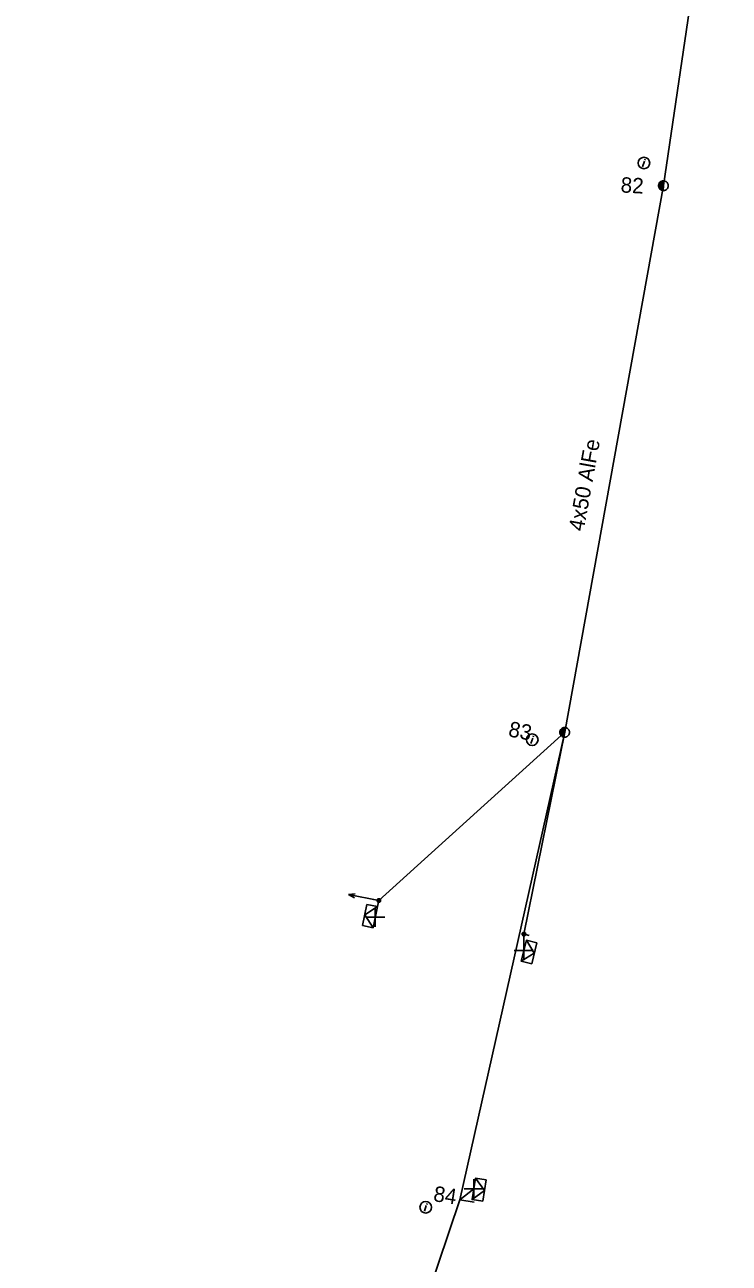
# Model space of a CAD drawing. Extents: x -544780 to -541582, y -1198995 to -1196551.
# Drawn here: x -542579.2 to -542533.5, y -1198149.8 to -1198069.4 of the extents above; entities that cross this region are included whole.
import ezdxf

# ---------------------------------------------------------------- set-up
doc = ezdxf.new("R2010")
doc.units = 0
for name, color, linetype in [('Vrstva 1', 7, 'Continuous'), ('Vrstva 10', 7, 'Continuous'), ('Vrstva 13', 7, 'Continuous'), ('Vrstva 14', 7, 'Continuous'), ('Vrstva 2', 7, 'Continuous'), ('Vrstva 31', 7, 'Continuous'), ('Vrstva 34', 7, 'Continuous'), ('Vrstva 36', 7, 'Continuous'), ('Vrstva 54', 7, 'Continuous'), ('Vrstva 8', 7, 'Continuous'), ('Vrstva 9', 7, 'Continuous')]:
    doc.layers.add(name, color=color, linetype=linetype)

# ---------------------------------------------------------------- blocks, each defined once
blk = doc.blocks.new('NN440')
at = {"layer": 'Vrstva 2'}
for points in [[(0.63, 0), (0.63, 0.06), (0.62, 0.13), (0.6, 0.19), (0.58, 0.25), (0.55, 0.31), (0.51, 0.37), (0.47, 0.42), (0.42, 0.46), (0.37, 0.51), (0.32, 0.54), (0.26, 0.57), (0.2, 0.59), (0.13, 0.61), (0.07, 0.62), (0, 0.63), (-0.06, 0.62), (-0.13, 0.61), (-0.19, 0.59), (-0.26, 0.57), (-0.31, 0.54), (-0.37, 0.51), (-0.42, 0.46), (-0.47, 0.42), (-0.51, 0.37), (-0.54, 0.31), (-0.57, 0.25), (-0.6, 0.19), (-0.62, 0.13), (-0.63, 0.06), (-0.63, 0), (-0.63, -0.07), (-0.62, -0.14), (-0.6, -0.2), (-0.57, -0.26), (-0.54, -0.32), (-0.51, -0.37), (-0.47, -0.43), (-0.42, -0.47), (-0.37, -0.51), (-0.31, -0.55), (-0.26, -0.58), (-0.19, -0.6), (-0.13, -0.62), (-0.06, -0.63), (0, -0.63), (0.07, -0.63), (0.13, -0.62), (0.2, -0.6), (0.26, -0.58), (0.32, -0.55), (0.37, -0.51), (0.42, -0.47), (0.47, -0.43), (0.51, -0.37), (0.55, -0.32), (0.58, -0.26), (0.6, -0.2), (0.62, -0.14), (0.63, -0.07), (0.63, 0)], [(-0.63, 0), (0.63, 0)], [(-0.6, -0.18), (0.57, -0.18)], [(-0.51, -0.32), (0.5, -0.32)], [(-0.37, -0.47), (0.35, -0.47)]]:
    blk.add_lwpolyline(points, dxfattribs=at)
blk = doc.blocks.new('NN560')
at = {"layer": 'Vrstva 2'}
for points in [[(1.999, -0.001), (1.59, 0.141)], [(0, -0.001), (1.999, -0.001)], [(1.999, -0.001), (1.59, -0.134)]]:
    blk.add_lwpolyline(points, dxfattribs=at)
blk = doc.blocks.new('NN770')
at = {"layer": 'Vrstva 10'}
for p, q in [((0.002, 0.187), (0.002, 0.263)), ((0.002, -0.276), (0.002, 0.111))]:
    blk.add_line(p, q, dxfattribs=at)
blk.add_circle((0, -0.008), 0.375, dxfattribs=at)
blk = doc.blocks.new('NN800')
at = {"layer": 'Vrstva 1'}
for points in [[(-0.442, 0.442), (0.442, -0.442)], [(-0.442, -0.442), (0.442, 0.442)]]:
    blk.add_lwpolyline(points, dxfattribs=at)
blk = doc.blocks.new('NN630')
at = {"layer": 'Vrstva 9'}
for points in [[(-0.003, -0.7), (-0.703, 0)], [(-0.703, -0.7), (-0.703, 0), (0.697, 0), (0.697, -0.7)], [(-0.703, -0.7), (0.697, -0.7)], [(-0.003, -0.7), (0.697, 0)]]:
    blk.add_lwpolyline(points, dxfattribs=at)
blk = doc.blocks.new('NN500')
at = {"layer": 'Vrstva 2'}
for points in [[(0, -0.24), (0.02, -0.23), (0.05, -0.23), (0.07, -0.22), (0.09, -0.22), (0.12, -0.2), (0.14, -0.19), (0.16, -0.18), (0.17, -0.16), (0.19, -0.14), (0.2, -0.12), (0.21, -0.1), (0.22, -0.07), (0.23, -0.05), (0.23, -0.02), (0.23, 0), (0.23, 0.02), (0.23, 0.05), (0.22, 0.07), (0.21, 0.1), (0.2, 0.12), (0.19, 0.14), (0.17, 0.16), (0.16, 0.17), (0.14, 0.19), (0.12, 0.2), (0.09, 0.21), (0.07, 0.22), (0.05, 0.23), (0.02, 0.23), (0, 0.23), (-0.03, 0.23), (-0.05, 0.23), (-0.07, 0.22), (-0.1, 0.21), (-0.12, 0.2), (-0.14, 0.19), (-0.16, 0.17), (-0.18, 0.16), (-0.19, 0.14), (-0.2, 0.12), (-0.22, 0.1), (-0.22, 0.07), (-0.23, 0.05), (-0.23, 0.02), (-0.24, 0), (-0.23, -0.02), (-0.23, -0.05), (-0.22, -0.07), (-0.22, -0.1), (-0.2, -0.12), (-0.19, -0.14), (-0.18, -0.16), (-0.16, -0.18), (-0.14, -0.19), (-0.12, -0.2), (-0.1, -0.22), (-0.07, -0.22), (-0.05, -0.23), (-0.03, -0.23), (0, -0.24)], [(0, -0.24), (0.02, -0.23), (0.05, -0.23), (0.07, -0.22), (0.09, -0.22), (0.12, -0.2), (0.14, -0.19), (0.16, -0.18), (0.17, -0.16), (0.19, -0.14), (0.2, -0.12), (0.21, -0.1), (0.22, -0.07), (0.23, -0.05), (0.23, -0.02), (0.23, 0), (0.23, 0.02), (0.23, 0.05), (0.22, 0.07), (0.21, 0.1), (0.2, 0.12), (0.19, 0.14), (0.17, 0.16), (0.16, 0.17), (0.14, 0.19), (0.12, 0.2), (0.09, 0.21), (0.07, 0.22), (0.05, 0.23), (0.02, 0.23), (0, 0.23), (-0.03, 0.23), (-0.05, 0.23), (-0.07, 0.22), (-0.1, 0.21), (-0.12, 0.2), (-0.14, 0.19), (-0.16, 0.17), (-0.18, 0.16), (-0.19, 0.14), (-0.2, 0.12), (-0.22, 0.1), (-0.22, 0.07), (-0.23, 0.05), (-0.23, 0.02), (-0.24, 0), (-0.23, -0.02), (-0.23, -0.05), (-0.22, -0.07), (-0.22, -0.1), (-0.2, -0.12), (-0.19, -0.14), (-0.18, -0.16), (-0.16, -0.18), (-0.14, -0.19), (-0.12, -0.2), (-0.1, -0.22), (-0.07, -0.22), (-0.05, -0.23), (-0.03, -0.23), (0, -0.24)], [(0, -0.21), (0.02, -0.2), (0.04, -0.2), (0.06, -0.2), (0.08, -0.19), (0.1, -0.18), (0.12, -0.17), (0.14, -0.15), (0.15, -0.14), (0.16, -0.12), (0.18, -0.1), (0.19, -0.08), (0.19, -0.06), (0.2, -0.04), (0.2, -0.02), (0.2, 0), (0.2, 0.02), (0.2, 0.04), (0.19, 0.06), (0.19, 0.08), (0.18, 0.1), (0.16, 0.12), (0.15, 0.14), (0.14, 0.15), (0.12, 0.17), (0.1, 0.18), (0.08, 0.19), (0.06, 0.19), (0.04, 0.2), (0.02, 0.2), (0, 0.2), (-0.02, 0.2), (-0.04, 0.2), (-0.06, 0.19), (-0.08, 0.19), (-0.1, 0.18), (-0.12, 0.17), (-0.14, 0.15), (-0.15, 0.14), (-0.17, 0.12), (-0.18, 0.1), (-0.19, 0.08), (-0.2, 0.06), (-0.2, 0.04), (-0.21, 0.02), (-0.21, 0), (-0.21, -0.02), (-0.2, -0.04), (-0.2, -0.06), (-0.19, -0.08), (-0.18, -0.1), (-0.17, -0.12), (-0.15, -0.14), (-0.14, -0.15), (-0.12, -0.17), (-0.1, -0.18), (-0.08, -0.19), (-0.06, -0.2), (-0.04, -0.2), (-0.02, -0.2), (0, -0.21)], [(0, -0.18), (0.02, -0.18), (0.04, -0.17), (0.05, -0.17), (0.07, -0.16), (0.09, -0.15), (0.1, -0.14), (0.12, -0.13), (0.13, -0.12), (0.14, -0.1), (0.15, -0.09), (0.16, -0.07), (0.17, -0.05), (0.17, -0.04), (0.17, -0.02), (0.17, 0), (0.17, 0.02), (0.17, 0.04), (0.17, 0.05), (0.16, 0.07), (0.15, 0.09), (0.14, 0.1), (0.13, 0.12), (0.12, 0.13), (0.1, 0.14), (0.09, 0.15), (0.07, 0.16), (0.05, 0.17), (0.04, 0.17), (0.02, 0.17), (0, 0.18), (-0.02, 0.17), (-0.04, 0.17), (-0.06, 0.17), (-0.07, 0.16), (-0.09, 0.15), (-0.1, 0.14), (-0.12, 0.13), (-0.13, 0.12), (-0.14, 0.1), (-0.15, 0.09), (-0.16, 0.07), (-0.17, 0.05), (-0.17, 0.04), (-0.18, 0.02), (-0.18, 0), (-0.18, -0.02), (-0.17, -0.04), (-0.17, -0.05), (-0.16, -0.07), (-0.15, -0.09), (-0.14, -0.1), (-0.13, -0.12), (-0.12, -0.13), (-0.1, -0.14), (-0.09, -0.15), (-0.07, -0.16), (-0.06, -0.17), (-0.04, -0.17), (-0.02, -0.18), (0, -0.18)], [(0, -0.15), (0.01, -0.15), (0.03, -0.14), (0.04, -0.14), (0.06, -0.13), (0.07, -0.13), (0.08, -0.12), (0.1, -0.11), (0.11, -0.1), (0.12, -0.09), (0.13, -0.07), (0.13, -0.06), (0.14, -0.05), (0.14, -0.03), (0.14, -0.02), (0.14, 0), (0.14, 0.01), (0.14, 0.03), (0.14, 0.04), (0.13, 0.06), (0.13, 0.07), (0.12, 0.09), (0.11, 0.1), (0.1, 0.11), (0.08, 0.12), (0.07, 0.13), (0.06, 0.13), (0.04, 0.14), (0.03, 0.14), (0.01, 0.14), (0, 0.15), (-0.02, 0.14), (-0.03, 0.14), (-0.05, 0.14), (-0.06, 0.13), (-0.07, 0.13), (-0.09, 0.12), (-0.1, 0.11), (-0.11, 0.1), (-0.12, 0.09), (-0.13, 0.07), (-0.13, 0.06), (-0.14, 0.04), (-0.14, 0.03), (-0.15, 0.01), (-0.15, 0), (-0.15, -0.02), (-0.14, -0.03), (-0.14, -0.05), (-0.13, -0.06), (-0.13, -0.07), (-0.12, -0.09), (-0.11, -0.1), (-0.1, -0.11), (-0.09, -0.12), (-0.07, -0.13), (-0.06, -0.13), (-0.05, -0.14), (-0.03, -0.14), (-0.02, -0.15), (0, -0.15)], [(0, -0.12), (0.01, -0.12), (0.02, -0.11), (0.03, -0.11), (0.05, -0.11), (0.06, -0.1), (0.07, -0.09), (0.08, -0.09), (0.09, -0.08), (0.09, -0.07), (0.1, -0.06), (0.11, -0.05), (0.11, -0.04), (0.11, -0.02), (0.11, -0.01), (0.12, 0), (0.11, 0.01), (0.11, 0.02), (0.11, 0.04), (0.11, 0.05), (0.1, 0.06), (0.09, 0.07), (0.09, 0.08), (0.08, 0.09), (0.07, 0.09), (0.06, 0.1), (0.05, 0.11), (0.03, 0.11), (0.02, 0.11), (0.01, 0.12), (0, 0.12), (-0.01, 0.12), (-0.03, 0.11), (-0.04, 0.11), (-0.05, 0.11), (-0.06, 0.1), (-0.07, 0.09), (-0.08, 0.09), (-0.09, 0.08), (-0.1, 0.07), (-0.1, 0.06), (-0.11, 0.05), (-0.11, 0.04), (-0.12, 0.02), (-0.12, 0.01), (-0.12, 0), (-0.12, -0.01), (-0.12, -0.02), (-0.11, -0.04), (-0.11, -0.05), (-0.1, -0.06), (-0.1, -0.07), (-0.09, -0.08), (-0.08, -0.09), (-0.07, -0.09), (-0.06, -0.1), (-0.05, -0.11), (-0.04, -0.11), (-0.03, -0.11), (-0.01, -0.12), (0, -0.12)], [(0, -0.09), (0.01, -0.09), (0.02, -0.09), (0.03, -0.08), (0.03, -0.08), (0.04, -0.08), (0.05, -0.07), (0.06, -0.07), (0.06, -0.06), (0.07, -0.05), (0.07, -0.04), (0.08, -0.04), (0.08, -0.03), (0.08, -0.02), (0.09, -0.01), (0.09, 0), (0.09, 0.01), (0.08, 0.02), (0.08, 0.03), (0.08, 0.03), (0.07, 0.04), (0.07, 0.05), (0.06, 0.06), (0.06, 0.06), (0.05, 0.07), (0.04, 0.07), (0.03, 0.08), (0.03, 0.08), (0.02, 0.08), (0.01, 0.09), (0, 0.09), (-0.01, 0.09), (-0.02, 0.08), (-0.03, 0.08), (-0.04, 0.08), (-0.04, 0.07), (-0.05, 0.07), (-0.06, 0.06), (-0.07, 0.06), (-0.07, 0.05), (-0.08, 0.04), (-0.08, 0.03), (-0.08, 0.03), (-0.09, 0.02), (-0.09, 0.01), (-0.09, 0), (-0.09, -0.01), (-0.09, -0.02), (-0.08, -0.03), (-0.08, -0.04), (-0.08, -0.04), (-0.07, -0.05), (-0.07, -0.06), (-0.06, -0.07), (-0.05, -0.07), (-0.04, -0.08), (-0.04, -0.08), (-0.03, -0.08), (-0.02, -0.09), (-0.01, -0.09), (0, -0.09)], [(0, -0.06), (0, -0.06), (0.01, -0.06), (0.02, -0.05), (0.02, -0.05), (0.03, -0.05), (0.03, -0.05), (0.04, -0.04), (0.04, -0.04), (0.05, -0.03), (0.05, -0.03), (0.05, -0.02), (0.05, -0.02), (0.05, -0.01), (0.06, -0.01), (0.06, 0), (0.06, 0.01), (0.05, 0.01), (0.05, 0.02), (0.05, 0.02), (0.05, 0.03), (0.05, 0.03), (0.04, 0.04), (0.04, 0.04), (0.03, 0.05), (0.03, 0.05), (0.02, 0.05), (0.02, 0.05), (0.01, 0.06), (0, 0.06), (0, 0.06), (-0.01, 0.06), (-0.01, 0.06), (-0.02, 0.05), (-0.02, 0.05), (-0.03, 0.05), (-0.03, 0.05), (-0.04, 0.04), (-0.04, 0.04), (-0.05, 0.03), (-0.05, 0.03), (-0.05, 0.02), (-0.06, 0.02), (-0.06, 0.01), (-0.06, 0.01), (-0.06, 0), (-0.06, -0.01), (-0.06, -0.01), (-0.06, -0.02), (-0.05, -0.02), (-0.05, -0.03), (-0.05, -0.03), (-0.04, -0.04), (-0.04, -0.04), (-0.03, -0.05), (-0.03, -0.05), (-0.02, -0.05), (-0.02, -0.05), (-0.01, -0.06), (-0.01, -0.06), (0, -0.06)], [(0, -0.03), (0, -0.03), (0, -0.03), (0.01, -0.03), (0.01, -0.03), (0.01, -0.02), (0.02, -0.02), (0.02, -0.02), (0.02, -0.02), (0.02, -0.02), (0.02, -0.01), (0.02, -0.01), (0.03, -0.01), (0.03, -0.01), (0.03, 0), (0.03, 0), (0.03, 0), (0.03, 0.01), (0.03, 0.01), (0.02, 0.01), (0.02, 0.01), (0.02, 0.02), (0.02, 0.02), (0.02, 0.02), (0.02, 0.02), (0.01, 0.02), (0.01, 0.02), (0.01, 0.03), (0, 0.03), (0, 0.03), (0, 0.03), (0, 0.03), (-0.01, 0.03), (-0.01, 0.03), (-0.01, 0.02), (-0.02, 0.02), (-0.02, 0.02), (-0.02, 0.02), (-0.02, 0.02), (-0.02, 0.02), (-0.03, 0.01), (-0.03, 0.01), (-0.03, 0.01), (-0.03, 0.01), (-0.03, 0), (-0.03, 0), (-0.03, 0), (-0.03, -0.01), (-0.03, -0.01), (-0.03, -0.01), (-0.03, -0.01), (-0.02, -0.02), (-0.02, -0.02), (-0.02, -0.02), (-0.02, -0.02), (-0.02, -0.02), (-0.01, -0.03), (-0.01, -0.03), (-0.01, -0.03), (0, -0.03), (0, -0.03)], [(0.23, 0), (0.7, 0)]]:
    blk.add_lwpolyline(points, dxfattribs=at)
blk = doc.blocks.new('NN510')
at = {"layer": 'Vrstva 2'}
blk.add_lwpolyline([(0.001, 0.002), (0.001, 0.939)], dxfattribs=at)

msp = doc.modelspace()

# ---------------------------------------------------------------- linework, layer by layer
at = {"layer": 'Vrstva 1'}
msp.add_lwpolyline([(-542579.193, -1198210.869), (-542574.44, -1198199.509), (-542567.826, -1198184.49), (-542565.717, -1198179.407), (-542555.939, -1198160.455), (-542550.955, -1198145.686), (-542544.149, -1198115.35), (-542537.742, -1198079.882), (-542533.471, -1198050.951)], dxfattribs=at)
at = {"layer": 'Vrstva 54'}
for points in [[(-542544.149, -1198115.35), (-542546.795, -1198128.441), (-542546.801, -1198129.515)], [(-542550.955, -1198145.686), (-542550.055, -1198144.972)]]:
    msp.add_lwpolyline(points, dxfattribs=at)
at = {"layer": 'Vrstva 8'}
msp.add_lwpolyline([(-542544.149, -1198115.35), (-542556.21, -1198126.261), (-542556.444, -1198127.346)], dxfattribs=at)

# ---------------------------------------------------------------- block references
at = {"layer": 'Vrstva 13'}
for name, p, xscale, yscale, rotation in [('NN440', (-542537.742, -1198079.883), 0.5, 0.5, -93.13695555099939), ('NN440', (-542544.15, -1198115.35), 0.5000000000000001, 0.4999999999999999, -101.28815554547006), ('NN500', (-542556.21, -1198126.261), 0.49999999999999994, 0.5, 167.94200003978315), ('NN500', (-542546.795, -1198128.441), 0.5, 0.5, -13.755999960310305)]:
    msp.add_blockref(name, p, dxfattribs=dict(at, xscale=xscale, yscale=yscale, rotation=rotation))
for name, p, rotation in [('NN560', (-542556.21, -1198126.261), 168.92345038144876), ('NN510', (-542550.955, -1198145.685), -98.91611668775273)]:
    msp.add_blockref(name, p, dxfattribs=dict(at, rotation=rotation))
at = {"layer": 'Vrstva 31'}
for p, rotation in [((-542556.444, -1198127.346), -102.05828887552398), ((-542546.801, -1198129.515), 76.24364162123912), ((-542550.055, -1198144.972), 81.0838832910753)]:
    msp.add_blockref('NN630', p, dxfattribs=dict(at, rotation=rotation))
at = {"layer": 'Vrstva 34', "rotation": 45}
for p in [(-542556.444, -1198127.346), (-542546.801, -1198129.515), (-542550.055, -1198144.972)]:
    msp.add_blockref('NN800', p, dxfattribs=at)
at = {"layer": 'Vrstva 36', "rotation": -18.70401939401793}
for p in [(-542539.006, -1198078.406), (-542546.255, -1198115.824), (-542553.168, -1198146.159)]:
    msp.add_blockref('NN770', p, dxfattribs=at)

# ---------------------------------------------------------------- texts
at = {"layer": 'Vrstva 14'}
for s, rotation, p in [('82', 356.863, (-542540.538, -1198080.321)), ('83', 348.712, (-542547.858, -1198115.599)), ('84', 351.084, (-542552.718, -1198145.757))]:
    msp.add_text(s, height=1, rotation=rotation, dxfattribs=at).set_placement(p)
at = {"layer": 'Vrstva 2'}
msp.add_text('4x50 AlFe', height=1, rotation=79.76, dxfattribs=at).set_placement((-542542.923, -1198102.35))

doc.saveas('drawing.dxf')
